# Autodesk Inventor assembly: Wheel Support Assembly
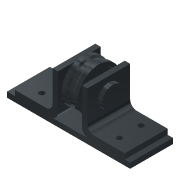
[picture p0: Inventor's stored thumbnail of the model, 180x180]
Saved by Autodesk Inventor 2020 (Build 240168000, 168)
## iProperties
Created: 2016-08
Part Number: Wheel Support Assembly
Document SubType Name: Assembly
Designer: Sandeep
Author: Sandeep
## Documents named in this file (5)
- D:\Autodesk Inventor_2020\Resources\Resources\Inventor_2020_tut\Inventor_2020_tut\c15_Inv_2020_tut\c15_Inv_tut_2020\c15_tut03_inv\Wheel Support Assembly.iam
- D:\Autodesk Inventor_2020\Resources\Resources\Inventor_2020_tut\Inventor_2020_tut\c15_Inv_2020_tut\c15_Inv_tut_2020\c15_tut03_inv\base.ipt
- D:\Autodesk Inventor_2020\Resources\Resources\Inventor_2020_tut\Inventor_2020_tut\c15_Inv_2020_tut\c15_Inv_tut_2020\c15_tut03_inv\Support.ipt
- D:\Autodesk Inventor_2020\Resources\Resources\Inventor_2020_tut\Inventor_2020_tut\c15_Inv_2020_tut\c15_Inv_tut_2020\c15_tut03_inv\Wheel.ipt
- D:\Autodesk Inventor_2020\Resources\Resources\Inventor_2020_tut\Inventor_2020_tut\c15_Inv_2020_tut\c15_Inv_tut_2020\c15_tut03_inv\Shoulder screw.ipt
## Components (5 placed, 4 different names)
1. base:1 — Insert:1, Mate:1, Insert:2, Mate:2
2. Support:1 — Insert:1, Mate:1, Insert:3
3. Support:2 — Insert:2, Mate:2, Mate:3, Mate:4
4. Wheel:1 — Insert:3
5. Shoulder screw:1 — Mate:3, Mate:4
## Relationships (7: Mate 4, Insert 3)
- Insert:1: base:1 ↔ Support:1
- Mate:1: base:1 ↔ Support:1
- Insert:2: base:1 ↔ Support:2
- Mate:2: base:1 ↔ Support:2
- Insert:3: Support:1 ↔ Wheel:1
- Mate:3: Support:2 ↔ Shoulder screw:1
- Mate:4: Support:2 ↔ Shoulder screw:1
